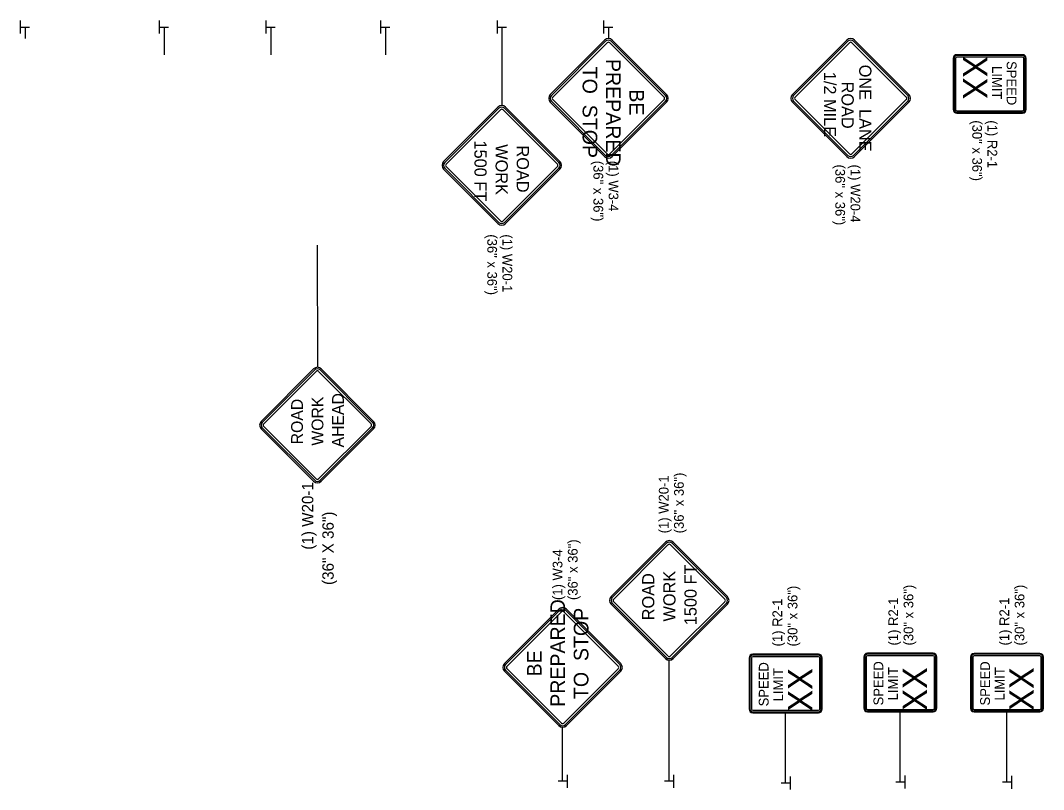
# Model space of a CAD drawing. Extents: x 1926586 to 1930787, y 596452 to 599566.
# Drawn here: x 1926586 to 1927216, y 596960 to 597433 of the extents above; entities that cross this region are included whole.
import ezdxf

# ---------------------------------------------------------------- set-up
doc = ezdxf.new("R2010")
doc.units = 0
for name, color, linetype in [('Default', 7, 'Continuous'), ('P_TC_Signs_Permanent', 7, 'Continuous'), ('P_TC_Signs_Temporary', 7, 'Continuous'), ('R_Border', 7, 'Continuous')]:
    doc.layers.add(name, color=color, linetype=linetype)

msp = doc.modelspace()

# ---------------------------------------------------------------- linework, layer by layer
at = {"layer": 'Default'}
for p, q in [((1926585.82, 597424.79), (1926585.82, 597432.79)), ((1926585.94, 597428.77), (1926591.4, 597428.77)), ((1926671.36, 597424.79), (1926671.36, 597432.79)), ((1926671.48, 597428.77), (1926676.95, 597428.77)), ((1926737.02, 597424.79), (1926737.02, 597432.79)), ((1926737.13, 597428.77), (1926742.6, 597428.77)), ((1926807.63, 597424.79), (1926807.63, 597432.79)), ((1926807.74, 597428.77), (1926813.21, 597428.77)), ((1926879.39, 597424.79), (1926879.39, 597432.79)), ((1926879.51, 597428.77), (1926884.98, 597428.77)), ((1926944.87, 597424.79), (1926944.87, 597432.79)), ((1926944.99, 597428.77), (1926950.45, 597428.77)), ((1926922.26, 596964.59), (1926916.79, 596964.59)), ((1926922.37, 596968.57), (1926922.37, 596960.56)), ((1926987.74, 596964.59), (1926982.27, 596964.59)), ((1926987.85, 596968.57), (1926987.85, 596960.56)), ((1927059.5, 596963.55), (1927054.04, 596963.55)), ((1927059.62, 596967.54), (1927059.62, 596959.53)), ((1927130.11, 596964.13), (1927124.65, 596964.13)), ((1927130.23, 596968.12), (1927130.23, 596960.11)), ((1927195.76, 596964.08), (1927190.3, 596964.08)), ((1927195.88, 596968.06), (1927195.88, 596960.05))]:
    msp.add_line(p, q, dxfattribs=at)
at = {"layer": 'P_TC_Signs_Permanent'}
for p, q in [((1926945.34, 597420.67), (1926911.93, 597387.26)), ((1926946, 597420.01), (1926912.59, 597386.6)), ((1926946.93, 597419.08), (1926913.52, 597385.67)), ((1926981.93, 597385.67), (1926948.52, 597419.08)), ((1926982.86, 597386.6), (1926949.45, 597420.01)), ((1926983.52, 597387.26), (1926950.11, 597420.67)), ((1927159.88, 597409.49), (1927159.88, 597377.99)), ((1927160.44, 597409.49), (1927160.44, 597377.99)), ((1927161.38, 597409.49), (1927161.38, 597377.99)), ((1927202.63, 597411.74), (1927162.13, 597411.74)), ((1927202.63, 597411.18), (1927162.13, 597411.18)), ((1927202.63, 597410.24), (1927162.13, 597410.24)), ((1927203.38, 597377.99), (1927203.38, 597409.49)), ((1927204.32, 597377.99), (1927204.32, 597409.49)), ((1927204.88, 597377.99), (1927204.88, 597409.49)), ((1926911.93, 597382.49), (1926945.34, 597349.07)), ((1926912.59, 597383.15), (1926946, 597349.74)), ((1926913.52, 597384.08), (1926946.93, 597350.67)), ((1926948.52, 597350.67), (1926981.93, 597384.08)), ((1926949.45, 597349.74), (1926982.86, 597383.15)), ((1926950.11, 597349.07), (1926983.52, 597382.49)), ((1927162.13, 597377.24), (1927202.63, 597377.24)), ((1927162.13, 597376.3), (1927202.63, 597376.3)), ((1927162.13, 597375.74), (1927202.63, 597375.74)), ((1926917.14, 597070.48), (1926883.73, 597037.06)), ((1926917.8, 597069.81), (1926884.39, 597036.4)), ((1926954.66, 597036.4), (1926921.25, 597069.81)), ((1926955.32, 597037.06), (1926921.91, 597070.48)), ((1926918.73, 597068.88), (1926885.32, 597035.47)), ((1926953.73, 597035.47), (1926920.32, 597068.88)), ((1927034.27, 597040.53), (1927034.27, 597009.03)), ((1927034.83, 597040.53), (1927034.83, 597009.03)), ((1927035.77, 597040.53), (1927035.77, 597009.03)), ((1927077.02, 597042.78), (1927036.52, 597042.78)), ((1927077.02, 597042.21), (1927036.52, 597042.21)), ((1927077.02, 597041.28), (1927036.52, 597041.28)), ((1927077.77, 597009.03), (1927077.77, 597040.53)), ((1927078.71, 597009.03), (1927078.71, 597040.53)), ((1927079.27, 597009.03), (1927079.27, 597040.53)), ((1927104.88, 597041.1), (1927104.88, 597009.6)), ((1927105.44, 597041.1), (1927105.44, 597009.6)), ((1927106.38, 597041.1), (1927106.38, 597009.6)), ((1927147.63, 597043.35), (1927107.13, 597043.35)), ((1927147.63, 597042.79), (1927107.13, 597042.79)), ((1927147.63, 597041.85), (1927107.13, 597041.85)), ((1927148.38, 597009.6), (1927148.38, 597041.1)), ((1927149.32, 597009.6), (1927149.32, 597041.1)), ((1927149.88, 597009.6), (1927149.88, 597041.1)), ((1927170.53, 597041.05), (1927170.53, 597009.55)), ((1927171.09, 597041.05), (1927171.09, 597009.55)), ((1927172.03, 597041.05), (1927172.03, 597009.55)), ((1927213.28, 597043.3), (1927172.78, 597043.3)), ((1927213.28, 597042.73), (1927172.78, 597042.73)), ((1927213.28, 597041.8), (1927172.78, 597041.8)), ((1927214.03, 597009.55), (1927214.03, 597041.05)), ((1927214.97, 597009.55), (1927214.97, 597041.05)), ((1927215.53, 597009.55), (1927215.53, 597041.05)), ((1926883.73, 597032.29), (1926917.14, 596998.88)), ((1926884.39, 597032.95), (1926917.8, 596999.54)), ((1926885.32, 597033.88), (1926918.73, 597000.47)), ((1926920.32, 597000.47), (1926953.73, 597033.88)), ((1926921.25, 596999.54), (1926954.66, 597032.95)), ((1926921.91, 596998.88), (1926955.32, 597032.29)), ((1927036.52, 597008.28), (1927077.02, 597008.28)), ((1927036.52, 597007.34), (1927077.02, 597007.34)), ((1927036.52, 597006.78), (1927077.02, 597006.78)), ((1927107.13, 597008.85), (1927147.63, 597008.85)), ((1927107.13, 597007.92), (1927147.63, 597007.92)), ((1927107.13, 597007.35), (1927147.63, 597007.35)), ((1927172.78, 597008.8), (1927213.28, 597008.8)), ((1927172.78, 597007.86), (1927213.28, 597007.86)), ((1927172.78, 597007.3), (1927213.28, 597007.3))]:
    msp.add_line(p, q, dxfattribs=at)
for centre, radius, start, end in [((1926947.72, 597418.28), 3.37, 45, 135), ((1926947.72, 597418.28), 2.44, 45, 135), ((1926947.72, 597418.28), 1.13, 45, 135), ((1927162.13, 597409.49), 2.25, 90, 180), ((1927162.13, 597409.49), 1.69, 90, 180), ((1927162.13, 597409.49), 0.75, 90, 180), ((1927202.63, 597409.49), 2.25, 360, 90), ((1927202.63, 597409.49), 1.69, 360, 90), ((1927202.63, 597409.49), 0.75, 360, 90), ((1926914.31, 597384.87), 3.37, 135, 225), ((1926914.31, 597384.87), 2.44, 135, 225), ((1926914.31, 597384.87), 1.13, 135, 225), ((1926981.13, 597384.87), 1.13, 315, 45), ((1926981.13, 597384.87), 2.44, 315, 45), ((1926981.13, 597384.87), 3.37, 315, 45), ((1927162.13, 597377.99), 2.25, 180, 270), ((1927162.13, 597377.99), 1.69, 180, 270), ((1927162.13, 597377.99), 0.75, 180, 270), ((1927202.63, 597377.99), 2.25, 270, 360), ((1927202.63, 597377.99), 1.69, 270, 360), ((1927202.63, 597377.99), 0.75, 270, 360), ((1926947.72, 597351.46), 3.37, 225, 315), ((1926947.72, 597351.46), 2.44, 225, 315), ((1926947.72, 597351.46), 1.13, 225, 315), ((1926919.52, 597068.09), 3.37, 45, 135), ((1926919.52, 597068.09), 2.44, 45, 135), ((1926919.52, 597068.09), 1.13, 45, 135), ((1927036.52, 597040.53), 2.25, 90, 180), ((1927036.52, 597040.53), 1.69, 90, 180), ((1927036.52, 597040.53), 0.75, 90, 180), ((1927077.02, 597040.53), 2.25, 360, 90), ((1927077.02, 597040.53), 1.69, 360, 90), ((1927077.02, 597040.53), 0.75, 360, 90), ((1927107.13, 597041.1), 2.25, 90, 180), ((1927107.13, 597041.1), 1.69, 90, 180), ((1927107.13, 597041.1), 0.75, 90, 180), ((1927147.63, 597041.1), 2.25, 360, 90), ((1927147.63, 597041.1), 1.69, 360, 90), ((1927147.63, 597041.1), 0.75, 360, 90), ((1927172.78, 597041.05), 2.25, 90, 180), ((1927172.78, 597041.05), 1.69, 90, 180), ((1927172.78, 597041.05), 0.75, 90, 180), ((1927213.28, 597041.05), 2.25, 360, 90), ((1927213.28, 597041.05), 1.69, 360, 90), ((1927213.28, 597041.05), 0.75, 360, 90), ((1926886.11, 597034.68), 3.37, 135, 225), ((1926886.11, 597034.68), 2.44, 135, 225), ((1926886.11, 597034.68), 1.13, 135, 225), ((1926952.93, 597034.68), 1.13, 315, 45), ((1926952.93, 597034.68), 2.44, 315, 45), ((1926952.93, 597034.68), 3.37, 315, 45), ((1927036.52, 597009.03), 2.25, 180, 270), ((1927036.52, 597009.03), 1.69, 180, 270), ((1927036.52, 597009.03), 0.75, 180, 270), ((1927077.02, 597009.03), 2.25, 270, 360), ((1927077.02, 597009.03), 1.69, 270, 360), ((1927077.02, 597009.03), 0.75, 270, 360), ((1927107.13, 597009.6), 2.25, 180, 270), ((1927107.13, 597009.6), 1.69, 180, 270), ((1927107.13, 597009.6), 0.75, 180, 270), ((1927147.63, 597009.6), 2.25, 270, 360), ((1927147.63, 597009.6), 1.69, 270, 360), ((1927147.63, 597009.6), 0.75, 270, 360), ((1927172.78, 597009.55), 2.25, 180, 270), ((1927172.78, 597009.55), 1.69, 180, 270), ((1927172.78, 597009.55), 0.75, 180, 270), ((1927213.28, 597009.55), 2.25, 270, 360), ((1927213.28, 597009.55), 1.69, 270, 360), ((1927213.28, 597009.55), 0.75, 270, 360), ((1926919.52, 597001.27), 1.13, 225, 315), ((1926919.52, 597001.27), 3.37, 225, 315), ((1926919.52, 597001.27), 2.44, 225, 315)]:
    msp.add_arc(centre, radius, start, end, dxfattribs=at)
at = {"layer": 'P_TC_Signs_Temporary'}
for p, q in [((1927061.04, 597387.26), (1927094.45, 597420.67)), ((1927061.7, 597386.59), (1927095.11, 597420.01)), ((1927062.63, 597385.67), (1927096.04, 597419.08)), ((1927097.63, 597419.08), (1927131.04, 597385.67)), ((1927098.56, 597420.01), (1927131.97, 597386.59)), ((1927099.22, 597420.67), (1927132.63, 597387.26)), ((1926846.27, 597346.01), (1926879.68, 597379.42)), ((1926846.94, 597345.35), (1926880.35, 597378.76)), ((1926883.79, 597378.76), (1926917.2, 597345.35)), ((1926884.46, 597379.42), (1926917.87, 597346.01)), ((1927094.45, 597349.07), (1927061.04, 597382.48)), ((1927095.11, 597349.74), (1927061.7, 597383.15)), ((1927096.04, 597350.66), (1927062.63, 597384.08)), ((1927131.04, 597384.08), (1927097.63, 597350.66)), ((1927131.97, 597383.15), (1927098.56, 597349.74)), ((1927132.63, 597382.48), (1927099.22, 597349.07)), ((1926847.86, 597344.42), (1926881.27, 597377.83)), ((1926882.87, 597377.83), (1926916.28, 597344.42)), ((1926879.68, 597307.83), (1926846.27, 597341.24)), ((1926880.35, 597308.49), (1926846.94, 597341.9)), ((1926881.27, 597309.42), (1926847.86, 597342.83)), ((1926916.28, 597342.83), (1926882.87, 597309.42)), ((1926917.2, 597341.9), (1926883.79, 597308.49)), ((1926917.87, 597341.24), (1926884.46, 597307.83)), ((1926766.28, 597218.4), (1926733.98, 597186.1)), ((1926766.92, 597217.76), (1926734.62, 597185.46)), ((1926767.82, 597216.86), (1926735.52, 597184.56)), ((1926801.65, 597184.56), (1926769.36, 597216.86)), ((1926802.55, 597185.46), (1926770.25, 597217.76)), ((1926803.19, 597186.1), (1926770.89, 597218.4)), ((1926735.52, 597183.03), (1926767.82, 597150.73)), ((1926769.36, 597150.73), (1926801.65, 597183.03)), ((1926733.98, 597181.49), (1926766.28, 597149.19)), ((1926734.62, 597182.13), (1926766.92, 597149.83)), ((1926770.25, 597149.83), (1926802.55, 597182.13)), ((1926770.89, 597149.19), (1926803.19, 597181.49)), ((1926949.38, 597078.31), (1926982.79, 597111.72)), ((1926950.04, 597077.65), (1926983.45, 597111.06)), ((1926950.97, 597076.72), (1926984.38, 597110.13)), ((1926985.97, 597110.13), (1927019.38, 597076.72)), ((1926986.9, 597111.06), (1927020.31, 597077.65)), ((1926987.56, 597111.72), (1927020.97, 597078.31)), ((1926982.79, 597040.13), (1926949.38, 597073.54)), ((1926983.45, 597040.79), (1926950.04, 597074.2)), ((1926984.38, 597041.72), (1926950.97, 597075.13)), ((1927019.38, 597075.13), (1926985.97, 597041.72)), ((1927020.31, 597074.2), (1926986.9, 597040.79)), ((1927020.97, 597073.54), (1926987.56, 597040.13))]:
    msp.add_line(p, q, dxfattribs=at)
for centre, radius, start, end in [((1927096.83, 597418.28), 3.37, 45, 135), ((1927096.83, 597418.28), 2.44, 45, 135), ((1927096.83, 597418.28), 1.12, 45, 135), ((1927063.42, 597384.87), 3.37, 135, 225), ((1927063.42, 597384.87), 2.44, 135, 225), ((1927063.42, 597384.87), 1.13, 135, 225), ((1927130.24, 597384.87), 1.13, 315, 45), ((1927130.24, 597384.87), 2.44, 315, 45), ((1927130.24, 597384.87), 3.37, 315, 45), ((1926882.07, 597377.04), 3.37, 45, 135), ((1926882.07, 597377.04), 2.44, 45, 135), ((1926882.07, 597377.04), 1.12, 45, 135), ((1927096.83, 597351.46), 3.37, 225, 315), ((1927096.83, 597351.46), 2.44, 225, 315), ((1927096.83, 597351.46), 1.12, 225, 315), ((1926848.66, 597343.63), 3.37, 135, 225), ((1926848.66, 597343.63), 2.44, 135, 225), ((1926848.66, 597343.63), 1.13, 135, 225), ((1926915.48, 597343.63), 1.13, 315, 45), ((1926915.48, 597343.63), 2.44, 315, 45), ((1926915.48, 597343.63), 3.37, 315, 45), ((1926882.07, 597310.22), 1.12, 225, 315), ((1926882.07, 597310.22), 3.37, 225, 315), ((1926882.07, 597310.22), 2.44, 225, 315), ((1926768.59, 597216.09), 3.26, 45, 135), ((1926768.59, 597216.09), 2.36, 45, 135), ((1926768.59, 597216.09), 1.09, 45, 135), ((1926736.29, 597183.79), 3.26, 135, 225), ((1926736.29, 597183.79), 2.36, 135, 225), ((1926736.29, 597183.79), 1.09, 135, 225), ((1926800.88, 597183.79), 1.09, 315, 45), ((1926800.88, 597183.79), 2.36, 315, 45), ((1926800.88, 597183.79), 3.26, 315, 45), ((1926768.59, 597151.5), 3.26, 225, 315), ((1926768.59, 597151.5), 2.36, 225, 315), ((1926768.59, 597151.5), 1.09, 225, 315), ((1926985.18, 597109.33), 3.37, 45, 135), ((1926985.18, 597109.33), 2.44, 45, 135), ((1926985.18, 597109.33), 1.12, 45, 135), ((1926951.77, 597075.92), 3.37, 135, 225), ((1926951.77, 597075.92), 2.44, 135, 225), ((1926951.77, 597075.92), 1.13, 135, 225), ((1927018.59, 597075.92), 1.13, 315, 45), ((1927018.59, 597075.92), 2.44, 315, 45), ((1927018.59, 597075.92), 3.37, 315, 45), ((1926985.18, 597042.51), 3.37, 225, 315), ((1926985.18, 597042.51), 2.44, 225, 315), ((1926985.18, 597042.51), 1.12, 225, 315)]:
    msp.add_arc(centre, radius, start, end, dxfattribs=at)
at = {"layer": 'R_Border'}
for p, q in [((1926588.67, 597428.77), (1926588.67, 597421.66)), ((1926674.21, 597428.77), (1926674.21, 597411.74)), ((1926739.87, 597428.77), (1926739.87, 597411.74)), ((1926810.48, 597428.77), (1926810.48, 597411.74)), ((1926882.07, 597428.77), (1926882.07, 597380.41)), ((1926947.72, 597428.77), (1926947.72, 597421.66)), ((1926768.47, 597294.58), (1926768.59, 597219.35)), ((1926985.18, 596964.59), (1926985.18, 597039.14)), ((1927056.77, 596963.55), (1927056.77, 597006.78)), ((1927127.38, 596964.13), (1927127.38, 597007.35)), ((1927193.03, 596964.08), (1927193.03, 597007.3)), ((1926919.52, 596964.59), (1926919.52, 596997.89))]:
    msp.add_line(p, q, dxfattribs=at)

# ---------------------------------------------------------------- texts
at = {"layer": 'Default'}
for s, p in [('(1) W20-1', (1926766.06, 597107.13)), ('(36" X 36")', (1926778.63, 597085.42))]:
    msp.add_text(s, height=7, rotation=90, dxfattribs=at).set_placement(p)
at = {"layer": 'P_TC_Signs_Permanent'}
for s, height, rotation, p in [('XX', 15, 270, (1927165.88, 597411.04)), ('LIMIT', 6, 270, (1927183.88, 597404.72)), ('SPEED', 6, 270, (1927192.88, 597407.81)), ('SPEED', 6, 90, (1927116.88, 597011.28)), ('SPEED', 6, 90, (1927182.53, 597011.23)), ('SPEED', 6, 90, (1927046.27, 597010.71)), ('LIMIT', 6, 90, (1927055.27, 597013.8)), ('XX', 15, 90, (1927073.27, 597007.48)), ('LIMIT', 6, 90, (1927125.88, 597014.37)), ('XX', 15, 90, (1927143.88, 597008.05)), ('LIMIT', 6, 90, (1927191.53, 597014.32)), ('XX', 15, 90, (1927209.53, 597008))]:
    msp.add_text(s, height=height, rotation=rotation, dxfattribs=at).set_placement(p)
at = {"layer": 'P_TC_Signs_Temporary'}
for s, height, rotation, p in [('TO  STOP', 9, 270, (1926931.85, 597404.34)), ('PREPARED', 9, 270, (1926946.25, 597409.11)), ('ONE  LANE', 7.5, 270, (1927102.08, 597405.57)), ('1/2 MILE', 7.5, 270, (1927080.33, 597401.19)), ('ROAD', 7.5, 270, (1927091.21, 597395.18)), ('BE', 9, 270, (1926960.65, 597390.42)), ('1500 FT', 7.5, 270, (1926865.24, 597358.92)), ('WORK', 7.5, 270, (1926878.26, 597356.62)), (' ROAD ', 7.5, 270, (1926891.28, 597358.65)), (' AHEAD ', 7.25, 90, (1926784.86, 597167.36)), (' ROAD ', 7.25, 90, (1926759.68, 597169.27)), ('WORK', 7.25, 90, (1926772.27, 597171.16)), ('1500 FT', 7.5, 90, (1927002.01, 597060.63)), (' ROAD ', 7.5, 90, (1926975.96, 597060.9)), ('WORK', 7.5, 90, (1926988.99, 597062.93)), ('PREPARED', 9, 90, (1926921, 597010.44)), ('TO  STOP', 9, 90, (1926935.4, 597015.21)), ('BE', 9, 90, (1926906.6, 597029.13))]:
    msp.add_text(s, height=height, rotation=rotation, dxfattribs=at).set_placement(p)
at = {"layer": 'R_Border'}
for s, height, rotation, p in [('(30" x 36")', 5.9996, 270, (1927171.66, 597371.36)), ('(1) R2-1', 6, 270, (1927181.02, 597371.36)), ('(36" x 36")', 5.9996, 270, (1926938.49, 597346.47)), ('(1) W3-4', 6, 270, (1926947.85, 597346.47)), ('(36" x 36")', 5.9996, 270, (1927087.36, 597344.14)), ('(1) W20-4', 6, 270, (1927096.72, 597344.14)), ('(36" x 36")', 5.9996, 270, (1926873.15, 597301.19)), ('(1) W20-1', 6, 270, (1926882.51, 597301.19)), ('(1) W20-1', 6, 90, (1926984.74, 597117.19)), ('(36" x 36")', 5.9996, 90, (1926994.1, 597117.19)), ('(36" x 36")', 5.9996, 90, (1926928.76, 597076.12)), ('(1) W3-4', 6, 90, (1926919.39, 597076.12)), ('(30" x 36")', 5.9996, 90, (1927064.05, 597047.58)), ('(30" x 36")', 5.9996, 90, (1927135.41, 597048.18)), ('(30" x 36")', 5.9996, 90, (1927203.75, 597048.18)), ('(1) R2-1', 6, 90, (1927054.69, 597047.58)), ('(1) R2-1', 6, 90, (1927126.05, 597048.18)), ('(1) R2-1', 6, 90, (1927194.39, 597048.18))]:
    msp.add_text(s, height=height, rotation=rotation, dxfattribs=at).set_placement(p)

doc.saveas('drawing.dxf')
